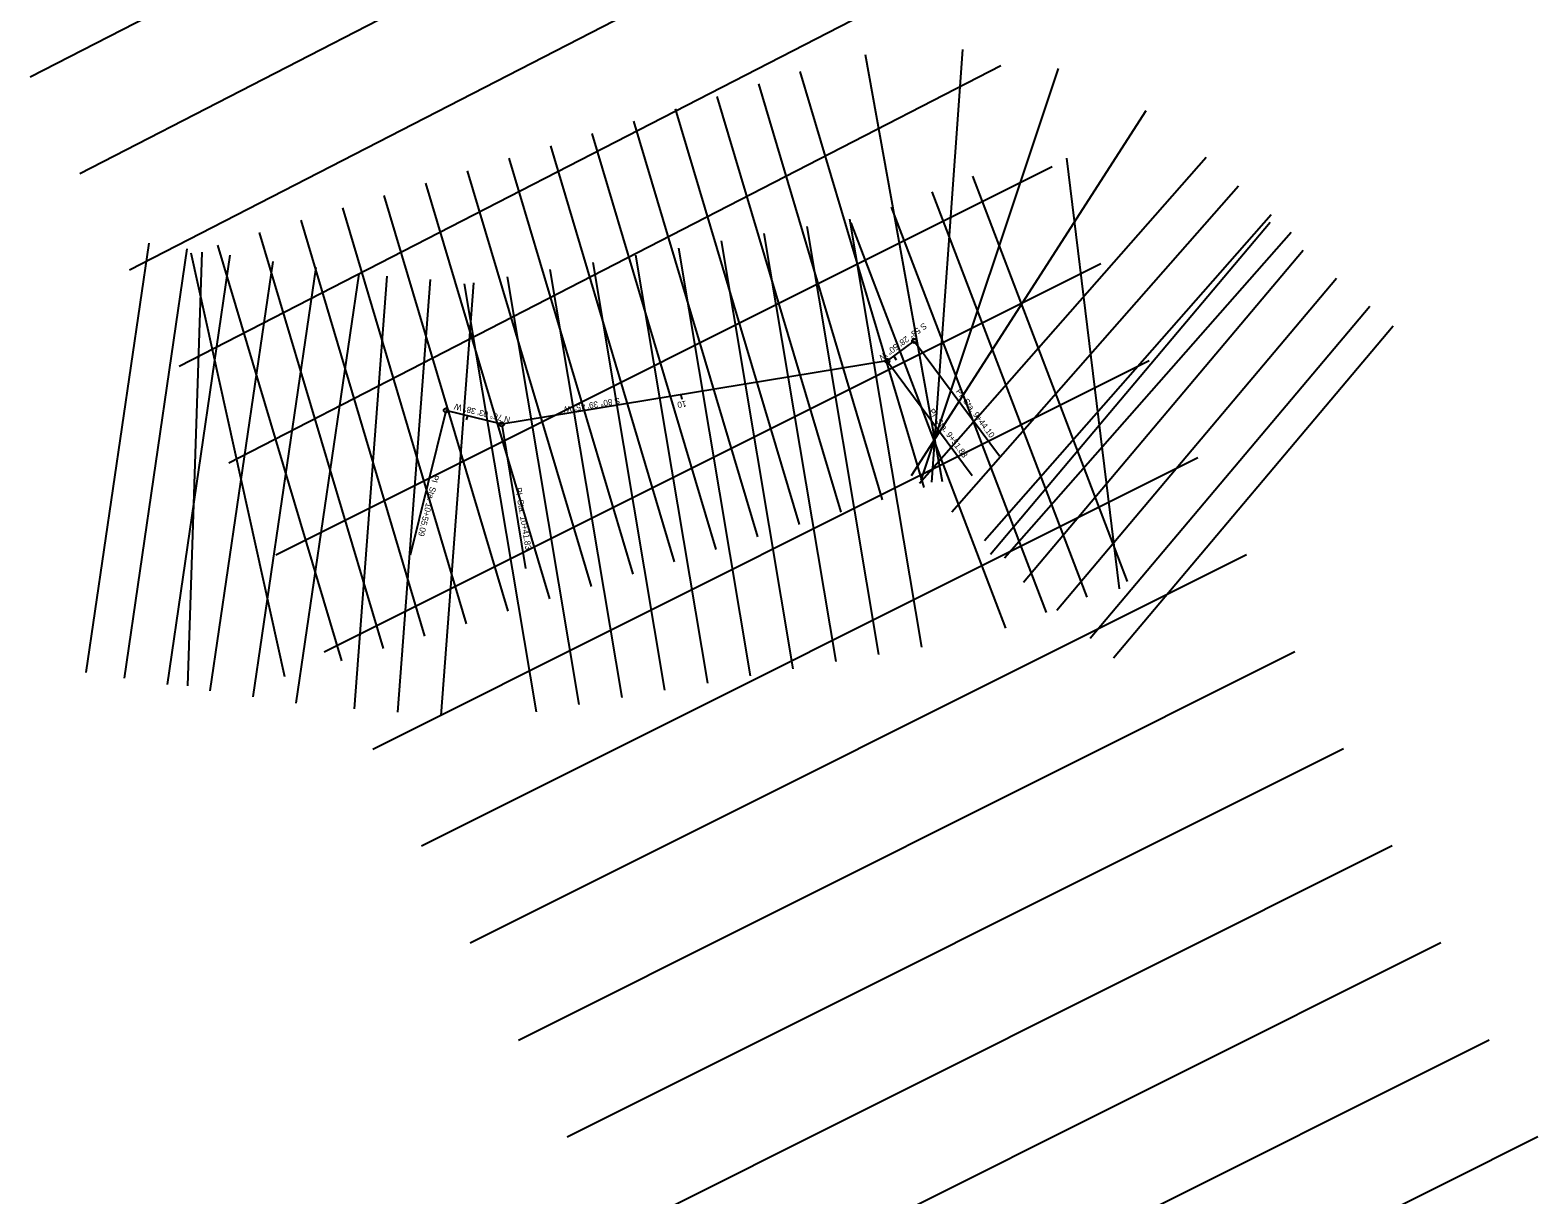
# Model space of a CAD drawing. Extents: x 1715627 to 1716641, y 394034 to 395892.
# Drawn here: x 1716108.7 to 1716456.1, y 394482.6 to 394751.1 of the extents above; entities that cross this region are included whole.
import ezdxf

# ---------------------------------------------------------------- set-up
doc = ezdxf.new("R2010")
doc.units = 0
for name, color, linetype in [('GE_P_CL_10', 7, 'Continuous'), ('GK_Patterns', 7, 'Continuous'), ('GK_Patterns2', 7, 'Continuous'), ('GK_Patterns3', 7, 'Continuous')]:
    doc.layers.add(name, color=color, linetype=linetype)

msp = doc.modelspace()

# ---------------------------------------------------------------- linework, layer by layer
at = {"layer": 'GE_P_CL_10'}
for p, q in [((1716312.41, 394679.43), (1716306.2, 394674.83)), ((1716312.71, 394679.03), (1716332.02, 394652.94)), ((1716306.2, 394674.83), (1716217.39, 394660.23)), ((1716306.5, 394674.43), (1716325.78, 394648.39)), ((1716307.67, 394675.92), (1716308.27, 394675.12)), ((1716258.67, 394667.02), (1716258.83, 394666.03)), ((1716217.39, 394660.23), (1716204.53, 394663.42)), ((1716204.4, 394662.94), (1716196.25, 394630.1)), ((1716209.46, 394662.2), (1716209.22, 394661.23)), ((1716217.47, 394659.74), (1716222.86, 394626.99))]:
    msp.add_line(p, q, dxfattribs=at)
for centre in [(1716312.41, 394679.43), (1716306.2, 394674.83), (1716204.53, 394663.42), (1716217.39, 394660.23)]:
    msp.add_circle(centre, 0.5, dxfattribs=at)
at = {"layer": 'GK_Patterns'}
for p, q in [((1716108.75, 394740.3), (1716286.57, 394831.83)), ((1716120.19, 394718.07), (1716298.01, 394809.6)), ((1716131.63, 394695.84), (1716309.45, 394787.37)), ((1716143.07, 394673.61), (1716320.9, 394765.14)), ((1716154.51, 394651.38), (1716332.34, 394742.91)), ((1716165.32, 394630.11), (1716344.17, 394719.61)), ((1716176.51, 394607.75), (1716355.36, 394697.26)), ((1716187.7, 394585.39), (1716366.55, 394674.9)), ((1716198.88, 394563.04), (1716377.74, 394652.54)), ((1716210.07, 394540.68), (1716388.93, 394630.19)), ((1716221.26, 394518.32), (1716400.11, 394607.83)), ((1716232.45, 394495.97), (1716411.3, 394585.47)), ((1716243.64, 394473.61), (1716422.49, 394563.12)), ((1716254.83, 394451.25), (1716433.68, 394540.76)), ((1716266.01, 394428.9), (1716444.87, 394518.4)), ((1716277.2, 394406.54), (1716456.06, 394496.05))]:
    msp.add_line(p, q, dxfattribs=at)
at = {"layer": 'GK_Patterns2'}
for p, q in [((1716359.67, 394622.32), (1716347.57, 394721.58)), ((1716361.55, 394623.96), (1716325.87, 394717.38)), ((1716352.21, 394620.39), (1716316.53, 394713.81)), ((1716342.87, 394616.82), (1716307.19, 394710.24)), ((1716304.27, 394607.2), (1716287.73, 394705.82)), ((1716314.13, 394608.85), (1716297.59, 394707.48)), ((1716333.52, 394613.25), (1716297.84, 394706.67)), ((1716329.96, 394630.29), (1716394.37, 394706.79)), ((1716121.66, 394603.02), (1716136.15, 394701.96)), ((1716284.54, 394603.89), (1716268, 394702.51)), ((1716294.41, 394605.55), (1716277.87, 394704.17)), ((1716130.45, 394601.73), (1716144.95, 394700.68)), ((1716140.35, 394600.28), (1716154.84, 394699.23)), ((1716264.82, 394600.58), (1716248.28, 394699.21)), ((1716274.68, 394602.24), (1716258.14, 394700.86)), ((1716337.61, 394623.85), (1716402.02, 394700.34)), ((1716150.24, 394598.83), (1716164.74, 394697.78)), ((1716160.14, 394597.38), (1716174.63, 394696.33)), ((1716170.03, 394595.93), (1716184.53, 394694.88)), ((1716245.1, 394597.27), (1716228.55, 394695.9)), ((1716254.96, 394598.93), (1716238.42, 394697.55)), ((1716183.46, 394594.64), (1716191.01, 394694.36)), ((1716193.43, 394593.89), (1716200.98, 394693.6)), ((1716203.4, 394593.14), (1716210.95, 394692.85)), ((1716225.37, 394593.97), (1716208.83, 394692.59)), ((1716235.23, 394595.62), (1716218.69, 394694.24)), ((1716345.26, 394617.41), (1716409.67, 394693.9)), ((1716352.91, 394610.97), (1716417.32, 394687.46)), ((1716358.34, 394606.4), (1716422.74, 394682.9))]:
    msp.add_line(p, q, dxfattribs=at)
at = {"layer": 'GK_Patterns3'}
for p, q in [((1716316.46, 394646.87), (1716323.61, 394746.61)), ((1716318.95, 394647), (1716301.2, 394745.42)), ((1716314.7, 394645.67), (1716286.16, 394741.51)), ((1716314.02, 394647.36), (1716345.62, 394742.23)), ((1716305.12, 394642.82), (1716276.58, 394738.66)), ((1716285.95, 394637.11), (1716257.41, 394732.95)), ((1716295.54, 394639.97), (1716266.99, 394735.8)), ((1716276.37, 394634.26), (1716247.82, 394730.1)), ((1716311.77, 394648.43), (1716365.86, 394732.54)), ((1716266.78, 394631.4), (1716238.24, 394727.24)), ((1716257.2, 394628.55), (1716228.66, 394724.39)), ((1716247.62, 394625.69), (1716219.07, 394721.53)), ((1716313.59, 394646.68), (1716379.62, 394721.78)), ((1716228.45, 394619.98), (1716199.9, 394715.82)), ((1716238.03, 394622.84), (1716209.49, 394718.68)), ((1716218.87, 394617.13), (1716190.32, 394712.97)), ((1716321.1, 394640.08), (1716387.13, 394715.18)), ((1716209.28, 394614.27), (1716180.74, 394710.11)), ((1716328.61, 394633.48), (1716394.64, 394708.58)), ((1716199.7, 394611.42), (1716171.15, 394707.26)), ((1716180.53, 394605.71), (1716151.98, 394701.55)), ((1716190.11, 394608.57), (1716161.57, 394704.4)), ((1716333.23, 394629.42), (1716399.26, 394704.52)), ((1716145.09, 394599.98), (1716148.34, 394699.93)), ((1716167.43, 394602.05), (1716145.86, 394699.7))]:
    msp.add_line(p, q, dxfattribs=at)

# ---------------------------------------------------------------- texts
at = {"layer": 'GE_P_CL_10'}
for s, rotation, p in [('S 53%%d 28\' 50" W', 216.5194, (1716314.64, 394683.7)), ('PI  Sta. 9+44.10', 306.5194, (1716321.9, 394667.79)), ('N 76%%d 03\' 38" W', 166.0607, (1716219.46, 394661.88)), ('S 80%%d 39\' 45" W', 189.3374, (1716244.49, 394666.39)), ('10', 189.3374, (1716259.79, 394665.68)), ('PI  Sta. 9+51.83', 306.5194, (1716315.69, 394663.19)), ('PI  Sta. 10+55.09', 256.0607, (1716201.59, 394648.7)), ('PI  Sta. 10+41.83', 279.3374, (1716220.52, 394645.54))]:
    msp.add_text(s, height=1.4, rotation=rotation, dxfattribs=at).set_placement(p)

doc.saveas('drawing.dxf')
